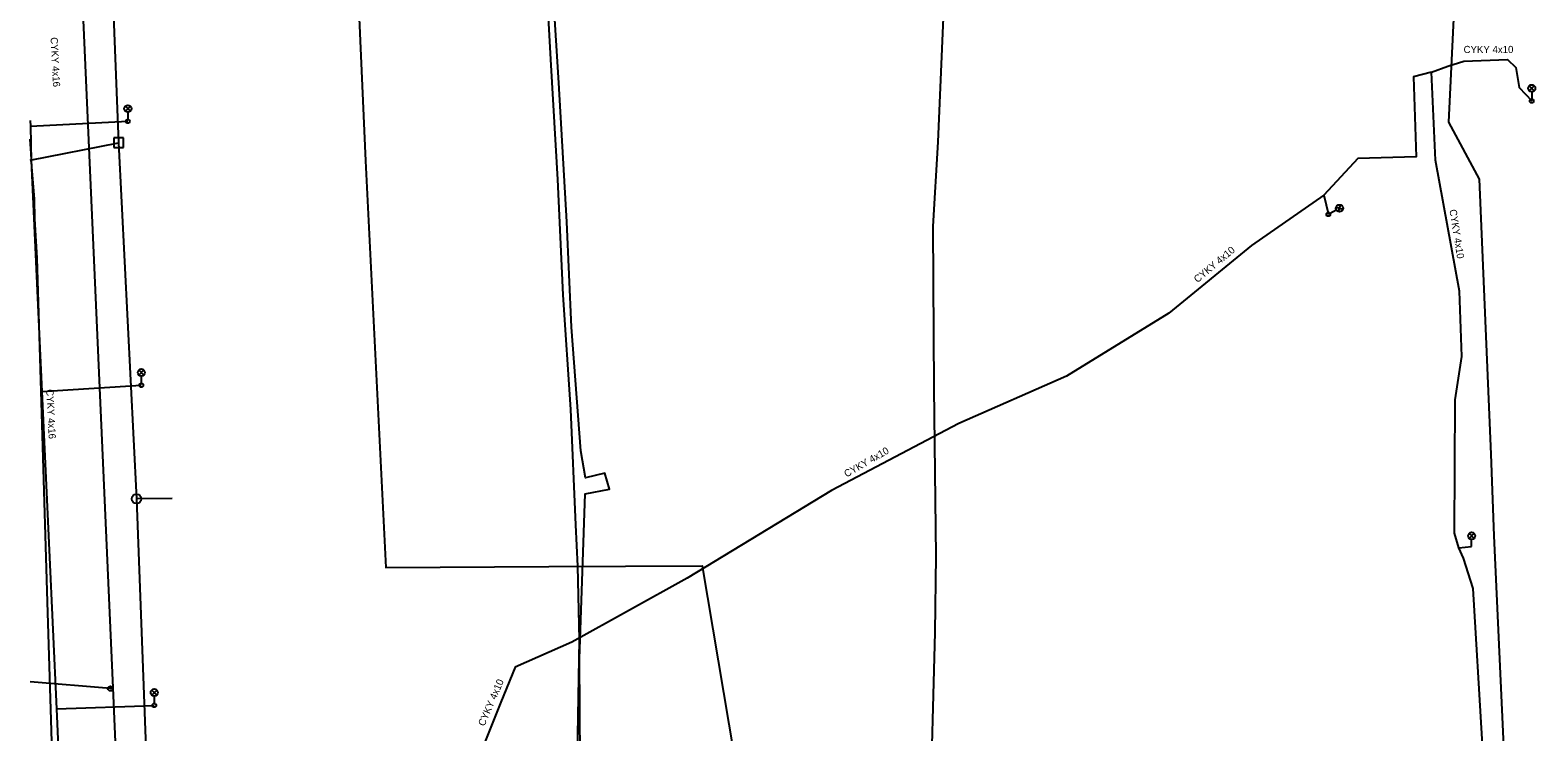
# Model space of a CAD drawing. Extents: x -736399 to -735926, y -1118992 to -1118244.
# Drawn here: x -736391.1 to -736234.1, y -1118673.7 to -1118600.6 of the extents above; entities that cross this region are included whole.
import ezdxf

# ---------------------------------------------------------------- set-up
doc = ezdxf.new("R2010")
doc.units = 0
for name, color, linetype in [('Kabelové vedení VO', 7, 'Continuous'), ('Kanalizační přípojky', 7, 'Continuous'), ('Kanalizační stoka', 7, 'Continuous'), ('Kanalizační šachty', 7, 'Continuous'), ('Osa trasy kynety', 7, 'Continuous'), ('Podz_ teplovodní potrubí', 7, 'Continuous'), ('Popis VO', 7, 'Continuous'), ('Povrchové znaky VO', 7, 'Continuous'), ('STL plynovod', 7, 'Continuous'), ('Vodovodní řad', 7, 'Continuous'), ('Vodovodní šoupata', 7, 'Continuous')]:
    doc.layers.add(name, color=color, linetype=linetype)

msp = doc.modelspace()

# ---------------------------------------------------------------- linework, layer by layer
at = {"layer": 'Kabelové vedení VO'}
for points in [[(-736245.17, -1118604.96), (-736243.48, -1118604.33), (-736241.79, -1118603.8), (-736237.26, -1118603.63), (-736236.39, -1118604.46), (-736236.03, -1118606.54), (-736234.74, -1118607.96)], [(-736245.17, -1118604.96), (-736247.04, -1118605.46), (-736246.77, -1118613.78), (-736252.85, -1118613.95), (-736256.37, -1118617.77)], [(-736242.31, -1118654.5), (-736242.76, -1118652.98), (-736242.7, -1118639.1), (-736242.02, -1118634.57), (-736242.27, -1118627.77), (-736244.76, -1118614.13), (-736245.17, -1118604.96)], [(-736391.05, -1118610.01), (-736391.03, -1118610.57)], [(-736391.03, -1118610.57), (-736380.88, -1118610.08)], [(-736391.03, -1118610.57), (-736390.95, -1118614.18)], [(-736390.95, -1118614.18), (-736391.05, -1118614.19)], [(-736390.95, -1118614.18), (-736389.83, -1118638.23)], [(-736256.37, -1118617.77), (-736263.92, -1118623.01), (-736272.5, -1118630.07), (-736283.17, -1118636.62), (-736294.38, -1118641.55), (-736307.63, -1118648.53), (-736322.64, -1118657.67), (-736334.66, -1118664.32), (-736340.57, -1118666.94), (-736342.07, -1118670.59), (-736344.5, -1118676.64), (-736346.53, -1118678.08), (-736347.39, -1118680.07)], [(-736256.37, -1118617.77), (-736255.91, -1118619.77)], [(-736389.83, -1118638.23), (-736379.48, -1118637.57)], [(-736389.83, -1118638.23), (-736388.3, -1118671.27)], [(-736240.82, -1118687.87), (-736240.88, -1118686.33), (-736239.51, -1118684.12), (-736239.91, -1118674.43), (-736240.85, -1118658.74), (-736241.83, -1118655.57), (-736242.31, -1118654.5), (-736240.99, -1118654.38)], [(-736388.3, -1118671.27), (-736378.13, -1118670.91)], [(-736388.3, -1118671.27), (-736387.76, -1118683.84)]]:
    msp.add_lwpolyline(points, dxfattribs=at)
at = {"layer": 'Kanalizační přípojky'}
msp.add_lwpolyline([(-736376.27, -1118649.37), (-736379.98, -1118649.4)], dxfattribs=at)
at = {"layer": 'Kanalizační stoka'}
for points in [[(-736383.18, -1118578.74), (-736381.85, -1118612.31)], [(-736391.05, -1118614.12), (-736381.85, -1118612.31)], [(-736381.85, -1118612.31), (-736379.98, -1118649.4)], [(-736379.98, -1118649.4), (-736378.58, -1118686.44)]]:
    msp.add_lwpolyline(points, dxfattribs=at)
at = {"layer": 'Kanalizační šachty'}
for p, q in [((-736381.35, -1118611.81), (-736382.35, -1118611.81)), ((-736382.35, -1118611.81), (-736382.35, -1118612.81)), ((-736381.35, -1118612.81), (-736381.35, -1118611.81)), ((-736382.35, -1118612.81), (-736381.35, -1118612.81))]:
    msp.add_line(p, q, dxfattribs=at)
msp.add_circle((-736379.98, -1118649.4), 0.5, dxfattribs=at)
at = {"layer": 'Osa trasy kynety'}
for points in [[(-736234.1, -1118752.15), (-736238.64, -1118653.26), (-736238.95, -1118644.76), (-736240.19, -1118616.12), (-736243.35, -1118610.17), (-736239.41, -1118528.25)], [(-736375.31, -1118826.62), (-736374.08, -1118826.62), (-736374.31, -1118812.67), (-736376.24, -1118777.74), (-736377.23, -1118753.46), (-736380.84, -1118698.19), (-736383.94, -1118696.05), (-736387.54, -1118695.77), (-736387.68, -1118694.09), (-736387.86, -1118690.1), (-736388.09, -1118687.92), (-736388.36, -1118685.1), (-736388.57, -1118683.41), (-736388.56, -1118682.52), (-736389.25, -1118660.13), (-736390.33, -1118624.32), (-736390.55, -1118620.23), (-736390.6, -1118618.14), (-736390.87, -1118614.81), (-736390.94, -1118613.43), (-736391.05, -1118611.93)], [(-736390.94, -1118613.43), (-736391.05, -1118613.44)]]:
    msp.add_lwpolyline(points, dxfattribs=at)
at = {"layer": 'Podz_ teplovodní potrubí'}
for points in [[(-736341.98, -1118691.48), (-736342.12, -1118688.41), (-736335.79, -1118688.26), (-736334.06, -1118688.25), (-736334.11, -1118677.96), (-736333.87, -1118664.1), (-736334.03, -1118656.4), (-736334.24, -1118652.09), (-736334.76, -1118640.11), (-736335.56, -1118628.14), (-736336.12, -1118616.15), (-736336.83, -1118604.23), (-736337.48, -1118592.37)], [(-736341.32, -1118692.06), (-736341.36, -1118688.91), (-736333.22, -1118688.74), (-736333.8, -1118676.63), (-736333.86, -1118666.05), (-736333.28, -1118648.87), (-736330.74, -1118648.4), (-736331.22, -1118646.72), (-736333.23, -1118647.2), (-736333.73, -1118644.39), (-736334.69, -1118631.52), (-736335.19, -1118620.56), (-736336.01, -1118606.08), (-736336.81, -1118593.37)]]:
    msp.add_lwpolyline(points, dxfattribs=at)
at = {"layer": 'Povrchové znaky VO'}
for p, q in [((-736235, -1118606.9), (-736234.48, -1118606.37)), ((-736234.47, -1118606.9), (-736235, -1118606.37)), ((-736234.74, -1118607.01), (-736234.74, -1118607.76)), ((-736381.14, -1118609.02), (-736380.62, -1118608.49)), ((-736380.61, -1118609.02), (-736381.14, -1118608.49)), ((-736380.88, -1118609.13), (-736380.88, -1118609.88)), ((-736255.08, -1118619.32), (-736255.73, -1118619.68)), ((-736255.1, -1118619.03), (-736254.39, -1118619.24)), ((-736254.84, -1118619.5), (-736254.63, -1118618.79)), ((-736379.74, -1118636.51), (-736379.22, -1118635.98)), ((-736379.21, -1118636.51), (-736379.74, -1118635.98)), ((-736379.48, -1118636.62), (-736379.48, -1118637.37)), ((-736241.25, -1118653.52), (-736240.73, -1118652.99)), ((-736240.72, -1118653.52), (-736241.25, -1118652.99)), ((-736240.99, -1118654.38), (-736240.99, -1118653.63)), ((-736378.39, -1118669.85), (-736377.87, -1118669.32)), ((-736377.86, -1118669.84), (-736378.39, -1118669.32)), ((-736378.13, -1118669.96), (-736378.13, -1118670.71))]:
    msp.add_line(p, q, dxfattribs=at)
for centre, radius in [((-736234.74, -1118606.64), 0.375), ((-736380.88, -1118608.76), 0.375), ((-736234.74, -1118607.96), 0.2), ((-736380.88, -1118610.08), 0.2), ((-736255.91, -1118619.77), 0.2), ((-736254.75, -1118619.14), 0.375), ((-736379.48, -1118636.25), 0.375), ((-736379.48, -1118637.57), 0.2), ((-736240.99, -1118653.26), 0.375), ((-736378.13, -1118669.58), 0.375), ((-736378.13, -1118670.91), 0.2)]:
    msp.add_circle(centre, radius, dxfattribs=at)
at = {"layer": 'STL plynovod'}
for points in [[(-736264.3, -1118324.54), (-736324.9, -1118327.07), (-736362.75, -1118328.92), (-736362.72, -1118353.43), (-736363.18, -1118442.48), (-736363.1, -1118443.08), (-736358.85, -1118498.73), (-736356.97, -1118538.37), (-736358.37, -1118564.14), (-736356.14, -1118614.21), (-736354.04, -1118656.54), (-736337.05, -1118656.45), (-736321.09, -1118656.36), (-736315.54, -1118689.35), (-736313.54, -1118701.53), (-736326.25, -1118704.41), (-736326.23, -1118704.84)], [(-736299.36, -1118790.52), (-736299.94, -1118773.18), (-736299.67, -1118765.93), (-736299.08, -1118759.56), (-736297.93, -1118742.79), (-736297.05, -1118727.2), (-736297.43, -1118706.52), (-736297.65, -1118693.4), (-736297.4, -1118693.16), (-736297.42, -1118692.81), (-736297.42, -1118688.46), (-736297.68, -1118688.03), (-736297.37, -1118682.82), (-736296.85, -1118663.31), (-736296.75, -1118655.32), (-736296.95, -1118637.86), (-736297.06, -1118621.04), (-736296.52, -1118612.23), (-736295.81, -1118595.2)]]:
    msp.add_lwpolyline(points, dxfattribs=at)
at = {"layer": 'Vodovodní řad'}
for points in [[(-736385.53, -1118599.54), (-736382.45, -1118669.1)], [(-736382.7, -1118669.16), (-736391.05, -1118668.46)], [(-736382.7, -1118669.16), (-736382.45, -1118669.1)], [(-736382.45, -1118669.1), (-736381.92, -1118681.17)]]:
    msp.add_lwpolyline(points, dxfattribs=at)
at = {"layer": 'Vodovodní šoupata'}
msp.add_circle((-736382.7, -1118669.16), 0.25, dxfattribs=at)

# ---------------------------------------------------------------- texts
at = {"layer": 'Popis VO'}
for s, rotation, p in [('CYKY 4x16', 272.8986, (-736388.93, -1118601.34)), ('CYKY 4x10', 279.1026, (-736243.31, -1118619.31)), ('CYKY 4x10', 40, (-736269.53, -1118626.94)), ('CYKY 4x16', 272.8986, (-736389.38, -1118638)), ('CYKY 4x10', 30, (-736306.06, -1118647.19)), ('CYKY 4x10', 66.7098, (-736343.77, -1118673.14))]:
    msp.add_text(s, height=0.75, rotation=rotation, dxfattribs=at).set_placement(p)
msp.add_text('CYKY 4x10', height=0.75, dxfattribs=at).set_placement((-736241.83, -1118602.97))

doc.saveas('drawing.dxf')
